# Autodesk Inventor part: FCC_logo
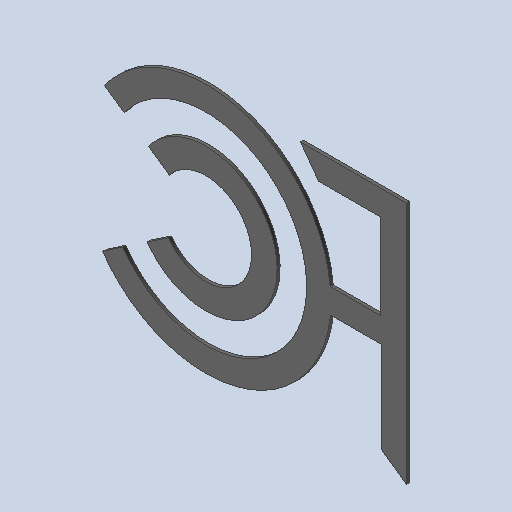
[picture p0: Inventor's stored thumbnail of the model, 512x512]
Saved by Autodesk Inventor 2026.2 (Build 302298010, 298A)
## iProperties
Created: 2026-10
Part Number: FCC_logo
Material: Générique
Document SubType Name: Modeling
Designer: mel
Density: 1 g/cm^3
Appearance: Par défaut
Author: mel
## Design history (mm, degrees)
feature "Base1"
feature "Base2"
node "Solide1"
node "Solide2"
